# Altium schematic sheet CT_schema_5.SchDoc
size 293 x 258 mm
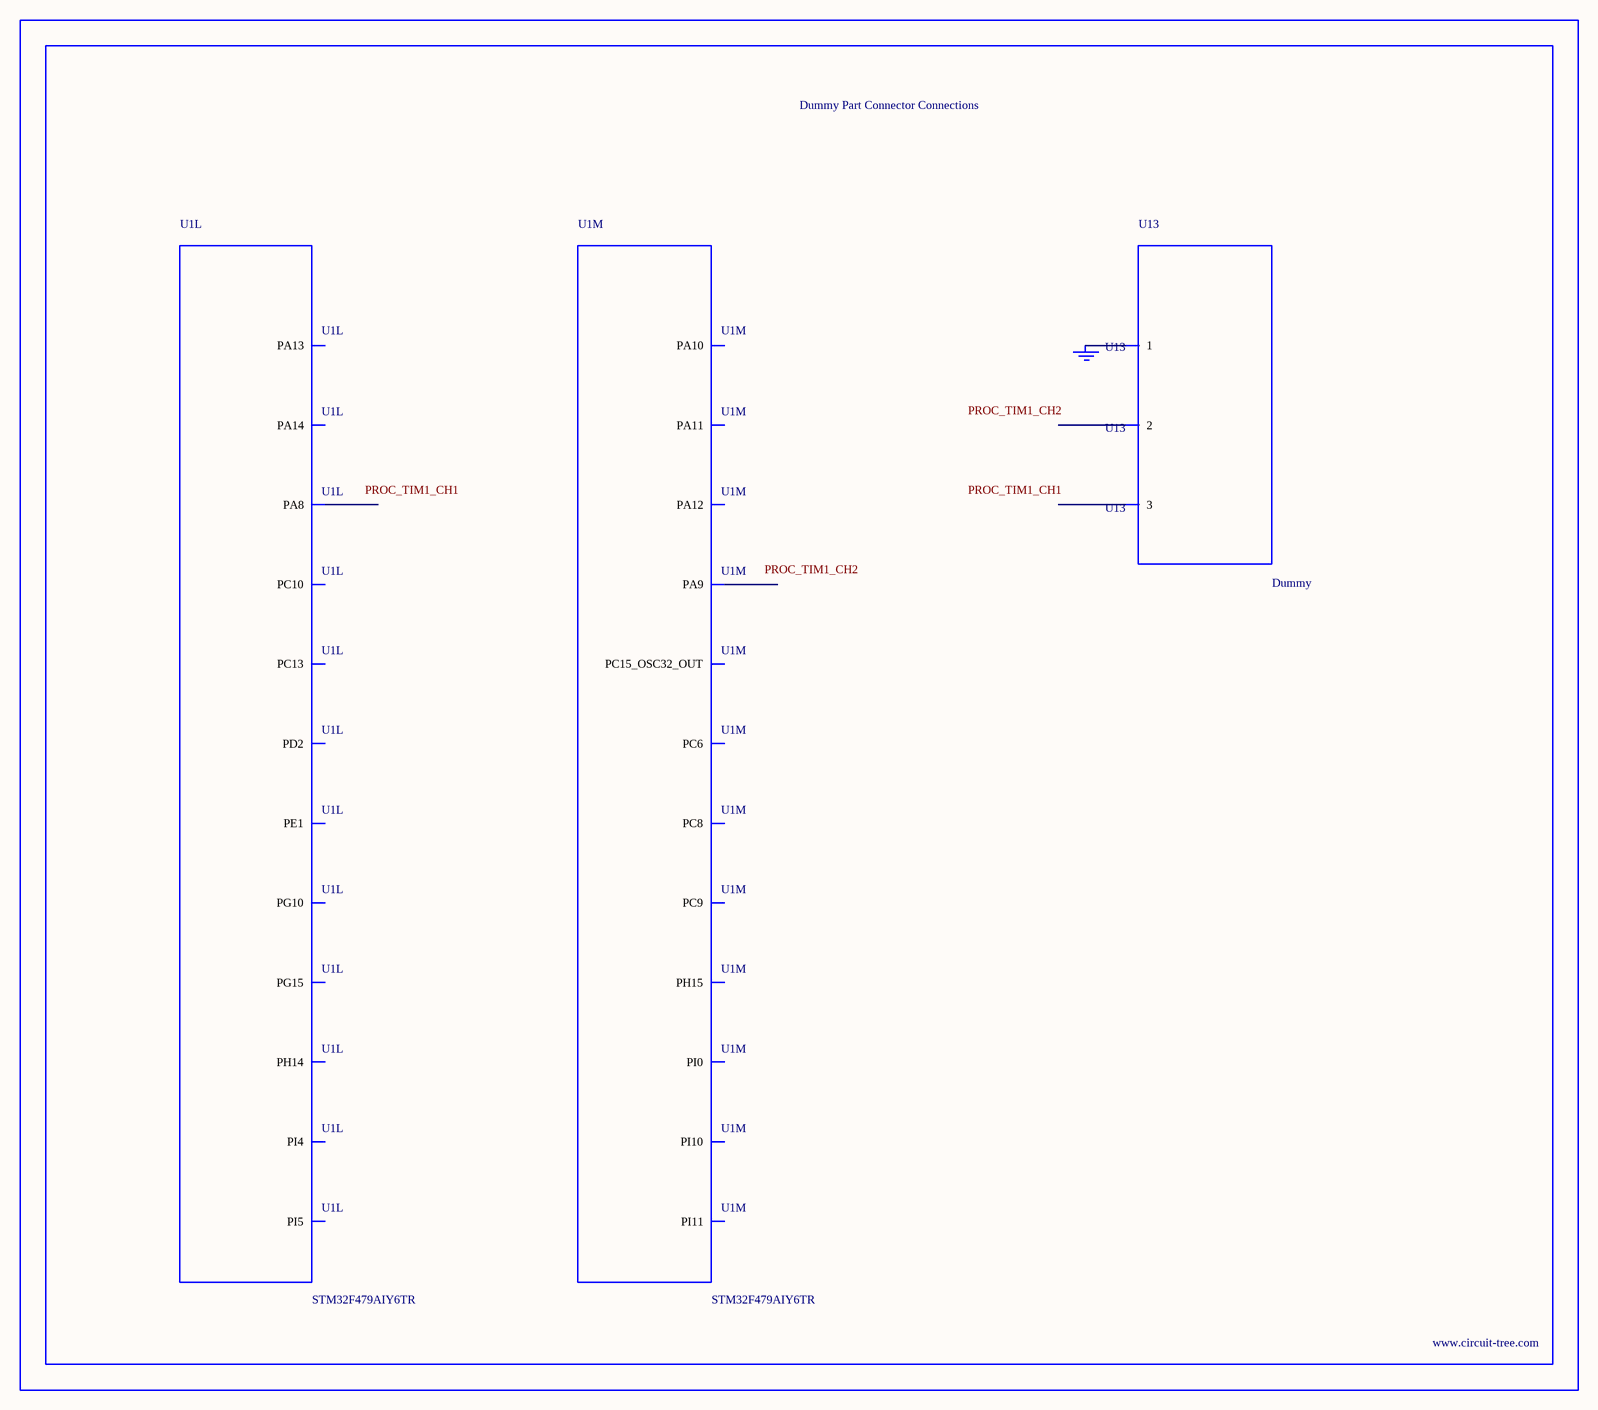
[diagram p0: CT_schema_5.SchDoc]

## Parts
BORDER4  (no value)
GND_INSTANCE_4_0  (no value)
U1  STM32F479AIY6TR  [WLCSP168]  (parts L,M of 13)
U13  Dummy  [DUMMY_PACKAGE_174]

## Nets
NetGND_INSTANCE_4_0_0: GND_INSTANCE_4_0.0(GND) U13.1

Not connected (* = marked no-connect by the designer): U1 C5(PD2) C7(PG10) C9(PE1) C10(PI5) D1(PA13) D3(PH14) D4(PA14) D5(PC10) D8(PG15) D10(PI4) D12(PC13) E1(PA8) E2(PA9) E3(PA10) E4(PH15) E5(PI0) E12(PC15_OSC32_OUT) F3(PC6) F4(PC8) F5(PC9) F6(PA12) F7(PA11) F10(PI10) F11(PI11); U13 2 3

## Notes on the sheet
- Labels drawn without touching a wire or pin: PROC_TIM1_CH1, PROC_TIM1_CH2

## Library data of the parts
BORDER4 = BORDER_PAGE4
GND_INSTANCE_4_0 = GND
